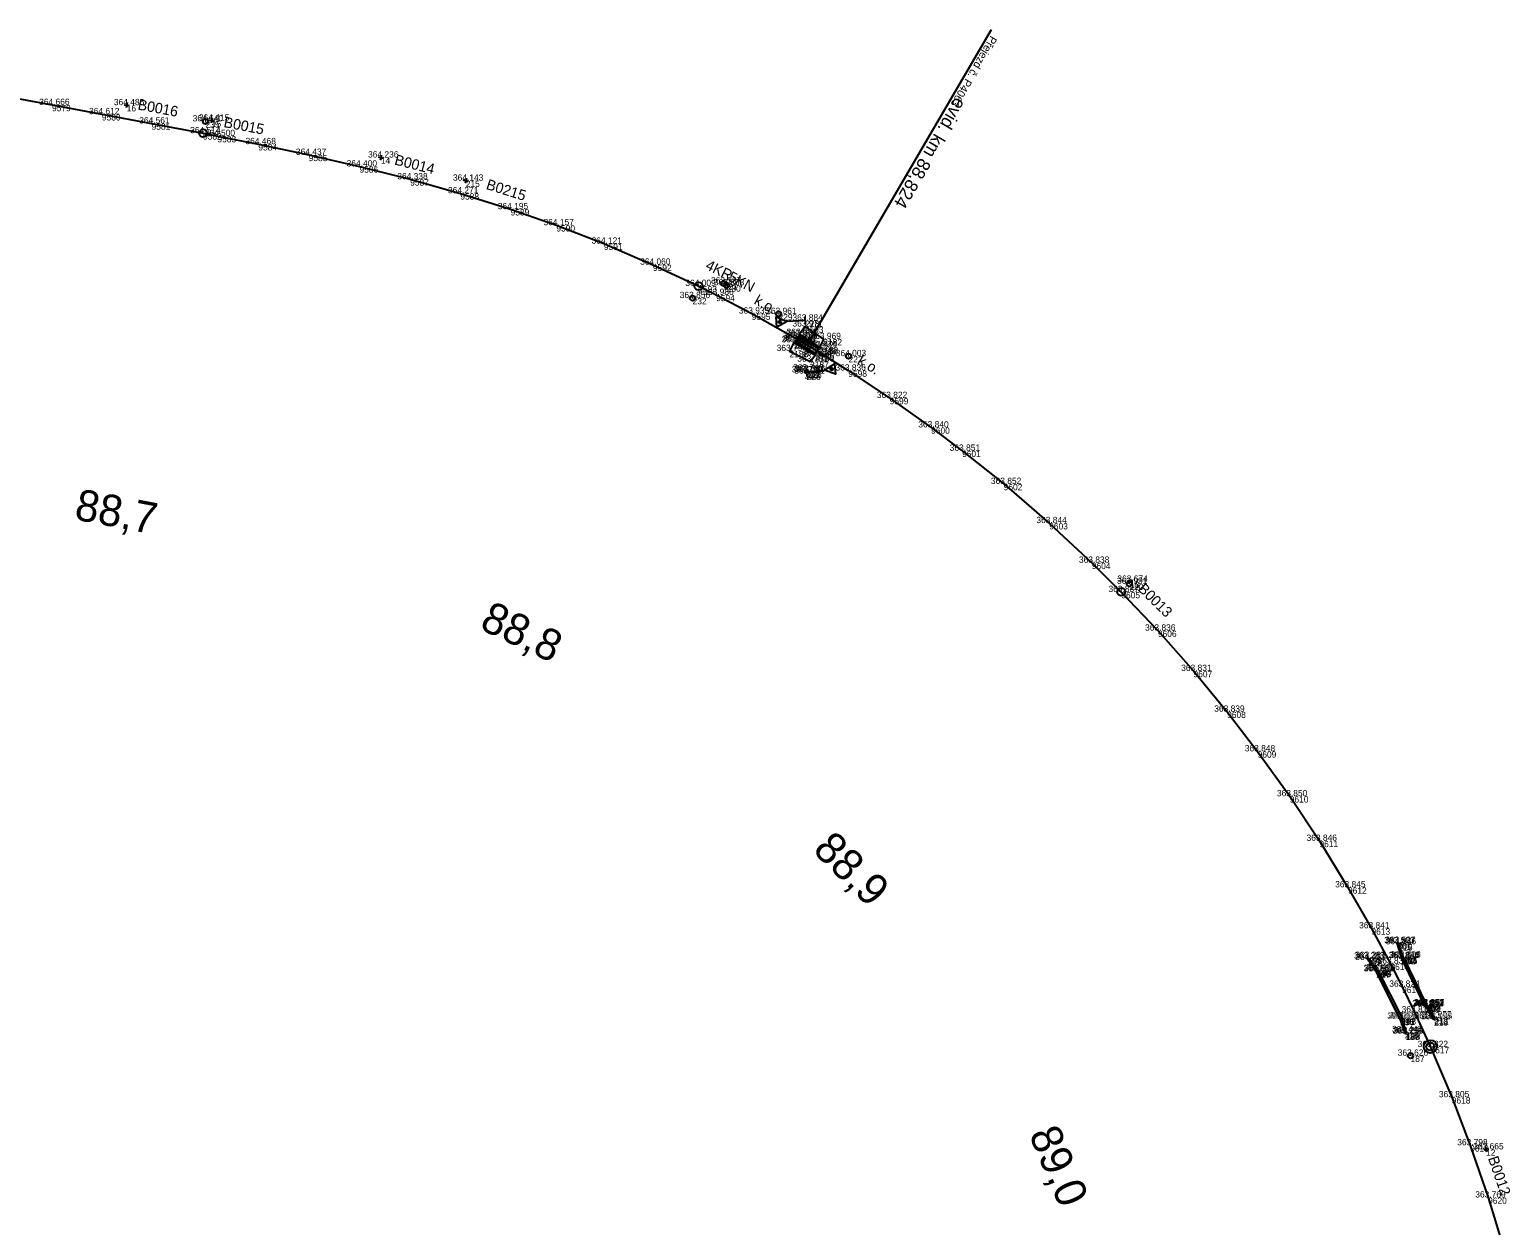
# Model space of a CAD drawing. Extents: x -599511 to -595511, y -1067427 to -1062061.
# Drawn here: x -595924.1 to -595641.5, y -1066766.1 to -1066537.9 of the extents above; entities that cross this region are included whole.
import ezdxf

# ---------------------------------------------------------------- set-up
doc = ezdxf.new("R2010")
doc.units = 0
for name, color, linetype in [('Vrstva 1', 7, 'Continuous'), ('Vrstva 12', 7, 'Continuous'), ('Vrstva 17', 7, 'Continuous'), ('Vrstva 18', 7, 'Continuous'), ('Vrstva 27', 7, 'Continuous'), ('Vrstva 4', 7, 'Continuous'), ('Vrstva 60', 7, 'Continuous'), ('Vrstva 61', 7, 'Continuous'), ('Vrstva 7', 7, 'Continuous')]:
    doc.layers.add(name, color=color, linetype=linetype)

msp = doc.modelspace()

# ---------------------------------------------------------------- linework, layer by layer
at = {"layer": 'Vrstva 1'}
msp.add_lwpolyline([(-595929.53, -1066550.51), (-595919.87, -1066552.29), (-595910.35, -1066554.06), (-595900.86, -1066555.83), (-595891.04, -1066557.7), (-595888.29, -1066558.23), (-595880.48, -1066559.78), (-595870.86, -1066561.82), (-595861.17, -1066564.04), (-595851.49, -1066566.49), (-595841.92, -1066569.17), (-595832.32, -1066572.19), (-595823.59, -1066575.25), (-595814.51, -1066578.77), (-595805.15, -1066582.78), (-595796.52, -1066586.85), (-595793.09, -1066588.55), (-595786.29, -1066592.11), (-595777.84, -1066596.85), (-595773.74, -1066599.3), (-595767.86, -1066602.99), (-595759.96, -1066608.23), (-595752.05, -1066613.85), (-595746.14, -1066618.3), (-595738.2, -1066624.64), (-595729.51, -1066632.11), (-595721.37, -1066639.68), (-595715.74, -1066645.26), (-595708.76, -1066652.62), (-595701.96, -1066660.32), (-595695.54, -1066668.1), (-595689.72, -1066675.67), (-595683.59, -1066684.23), (-595677.93, -1066692.75), (-595672.47, -1066701.63), (-595667.99, -1066709.45), (-595664.37, -1066716.2), (-595662.14, -1066720.6), (-595659.78, -1066725.47), (-595656.72, -1066732.11), (-595652.66, -1066741.68), (-595649.15, -1066750.86), (-595645.72, -1066760.82), (-595642.55, -1066771.26)], dxfattribs=at)
at = {"layer": 'Vrstva 12'}
msp.add_lwpolyline([(-595776.2, -1066603.35), (-595775.95, -1066602.97), (-595775.59, -1066603.18), (-595775.81, -1066603.57)], close=True, dxfattribs=at)
at = {"layer": 'Vrstva 17'}
for points in [[(-595662.83, -1066712.48), (-595661.92, -1066715.05), (-595657.47, -1066724.14), (-595656.02, -1066726.45)], [(-595661.64, -1066729.26), (-595662.5, -1066726.68), (-595667.04, -1066717.65), (-595668.63, -1066715.48)]]:
    msp.add_lwpolyline(points, dxfattribs=at)
at = {"layer": 'Vrstva 18'}
for points in [[(-595655.9, -1066726.71), (-595656.06, -1066726.82), (-595657.62, -1066724.3), (-595657.76, -1066724.35), (-595662.27, -1066715.13), (-595662.17, -1066715.11), (-595663.1, -1066712.29), (-595662.93, -1066712.21), (-595661.99, -1066715.04), (-595661.89, -1066715), (-595657.41, -1066724.14), (-595657.51, -1066724.18)], [(-595661.33, -1066729.49), (-595661.52, -1066729.55), (-595662.44, -1066726.72), (-595662.52, -1066726.75), (-595667.12, -1066717.66), (-595667.04, -1066717.6), (-595668.86, -1066715.22), (-595668.65, -1066715.08), (-595666.88, -1066717.49), (-595666.77, -1066717.44), (-595662.15, -1066726.6), (-595662.25, -1066726.66)]]:
    msp.add_lwpolyline(points, close=True, dxfattribs=at)
at = {"layer": 'Vrstva 27'}
for p, q in [((-595791.66, -1066586.35), (-595791.58, -1066586.39)), ((-595791.11, -1066586.7), (-595791.02, -1066586.75)), ((-595781.21, -1066592.17), (-595781.13, -1066592.22)), ((-595767.85, -1066600.22), (-595767.77, -1066600.27))]:
    msp.add_line(p, q, dxfattribs=at)
for centre in [(-595791.62, -1066586.37), (-595791.07, -1066586.73), (-595781.17, -1066592.19), (-595767.81, -1066600.24)]:
    msp.add_circle(centre, 0.5, dxfattribs=at)
at = {"layer": 'Vrstva 4'}
for p, q in [((-595775.69, -1066598.13), (-595740.51, -1066537.92)), ((-595776.05, -1066594.22), (-595776.12, -1066592.67)), ((-595780.74, -1066593.88), (-595781.1, -1066593.55)), ((-595775.91, -1066602.47), (-595775.76, -1066604.02)), ((-595771.21, -1066602.57), (-595770.84, -1066602.88))]:
    msp.add_line(p, q, dxfattribs=at)
for points in [[(-595776.08, -1066593.45), (-595779.56, -1066593.62), (-595781.51, -1066594.7), (-595781.62, -1066592.71), (-595779.56, -1066593.62)], [(-595775.84, -1066603.24), (-595772.38, -1066602.89), (-595770.48, -1066601.71), (-595770.28, -1066603.7), (-595772.38, -1066602.89)]]:
    msp.add_lwpolyline(points, dxfattribs=at)
for points in [[(-595777.29, -1066596.2), (-595776.17, -1066594.6), (-595772.62, -1066596.98), (-595773.36, -1066598.55)], [(-595775.15, -1066601.29), (-595774.16, -1066600.06), (-595778.24, -1066597.61), (-595779.09, -1066599.26)], [(-595777.95, -1066597.43), (-595777.4, -1066596.46), (-595773.53, -1066598.78), (-595774.11, -1066599.73)]]:
    msp.add_lwpolyline(points, close=True, dxfattribs=at)
for centre in [(-595780.92, -1066593.72), (-595771.03, -1066602.73)]:
    msp.add_circle(centre, 0.248, dxfattribs=at)
at = {"layer": 'Vrstva 60'}
for p, q in [((-595919.87, -1066552.29), (-595919.87, -1066552.29)), ((-595905.61, -1066552.34), (-595905.61, -1066552.34)), ((-595910.35, -1066554.06), (-595910.35, -1066554.06)), ((-595900.86, -1066555.83), (-595900.86, -1066555.83)), ((-595890.57, -1066555.44), (-595890.57, -1066555.44)), ((-595889.37, -1066555.28), (-595889.37, -1066555.28)), ((-595891.04, -1066557.7), (-595891.04, -1066557.7)), ((-595888.29, -1066558.23), (-595888.29, -1066558.23)), ((-595880.48, -1066559.78), (-595880.48, -1066559.78)), ((-595870.86, -1066561.82), (-595870.86, -1066561.82)), ((-595861.17, -1066564.04), (-595861.17, -1066564.04)), ((-595857.09, -1066562.33), (-595857.09, -1066562.33)), ((-595851.49, -1066566.49), (-595851.49, -1066566.49)), ((-595840.88, -1066566.75), (-595840.88, -1066566.75)), ((-595841.92, -1066569.17), (-595841.92, -1066569.17)), ((-595832.32, -1066572.19), (-595832.32, -1066572.19)), ((-595823.59, -1066575.25), (-595823.59, -1066575.25)), ((-595814.51, -1066578.77), (-595814.51, -1066578.77)), ((-595805.15, -1066582.78), (-595805.15, -1066582.78)), ((-595796.52, -1066586.85), (-595796.52, -1066586.85)), ((-595791.62, -1066586.37), (-595791.62, -1066586.37)), ((-595791.07, -1066586.73), (-595791.07, -1066586.73)), ((-595797.58, -1066589.16), (-595797.58, -1066589.16)), ((-595793.09, -1066588.55), (-595793.09, -1066588.55)), ((-595786.29, -1066592.11), (-595786.29, -1066592.11)), ((-595781.17, -1066592.19), (-595781.17, -1066592.19)), ((-595776.17, -1066594.6), (-595776.17, -1066594.6)), ((-595776.08, -1066593.45), (-595776.08, -1066593.45)), ((-595778.24, -1066597.61), (-595778.24, -1066597.61)), ((-595777.95, -1066597.43), (-595777.95, -1066597.43)), ((-595777.84, -1066596.85), (-595777.84, -1066596.85)), ((-595777.4, -1066596.46), (-595777.4, -1066596.46)), ((-595777.29, -1066596.2), (-595777.29, -1066596.2)), ((-595773.53, -1066598.78), (-595773.53, -1066598.78)), ((-595773.36, -1066598.55), (-595773.36, -1066598.55)), ((-595772.62, -1066596.98), (-595772.62, -1066596.98)), ((-595779.09, -1066599.26), (-595779.09, -1066599.26)), ((-595775.15, -1066601.29), (-595775.15, -1066601.29)), ((-595774.16, -1066600.06), (-595774.16, -1066600.06)), ((-595774.11, -1066599.73), (-595774.11, -1066599.73)), ((-595773.74, -1066599.3), (-595773.74, -1066599.3)), ((-595767.81, -1066600.24), (-595767.81, -1066600.24)), ((-595776.2, -1066603.35), (-595776.2, -1066603.35)), ((-595775.95, -1066602.97), (-595775.95, -1066602.97)), ((-595775.84, -1066603.24), (-595775.84, -1066603.24)), ((-595775.81, -1066603.57), (-595775.81, -1066603.57)), ((-595775.59, -1066603.18), (-595775.59, -1066603.18)), ((-595767.86, -1066602.99), (-595767.86, -1066602.99)), ((-595759.96, -1066608.23), (-595759.96, -1066608.23)), ((-595752.05, -1066613.85), (-595752.05, -1066613.85)), ((-595746.14, -1066618.3), (-595746.14, -1066618.3)), ((-595738.2, -1066624.64), (-595738.2, -1066624.64)), ((-595729.51, -1066632.11), (-595729.51, -1066632.11)), ((-595721.37, -1066639.68), (-595721.37, -1066639.68)), ((-595714.21, -1066643.69), (-595714.21, -1066643.69)), ((-595714.05, -1066643.3), (-595714.05, -1066643.3)), ((-595715.74, -1066645.26), (-595715.74, -1066645.26)), ((-595708.76, -1066652.62), (-595708.76, -1066652.62)), ((-595701.96, -1066660.32), (-595701.96, -1066660.32)), ((-595695.54, -1066668.1), (-595695.54, -1066668.1)), ((-595689.72, -1066675.67), (-595689.72, -1066675.67)), ((-595683.59, -1066684.23), (-595683.59, -1066684.23)), ((-595677.93, -1066692.75), (-595677.93, -1066692.75)), ((-595672.47, -1066701.63), (-595672.47, -1066701.63)), ((-595667.99, -1066709.45), (-595667.99, -1066709.45)), ((-595663.1, -1066712.29), (-595663.1, -1066712.29)), ((-595662.93, -1066712.21), (-595662.93, -1066712.21)), ((-595662.83, -1066712.48), (-595662.83, -1066712.48)), ((-595668.86, -1066715.22), (-595668.86, -1066715.22)), ((-595668.65, -1066715.08), (-595668.65, -1066715.08)), ((-595668.63, -1066715.48), (-595668.63, -1066715.48)), ((-595666.88, -1066717.49), (-595666.88, -1066717.49)), ((-595666.77, -1066717.44), (-595666.77, -1066717.44)), ((-595664.37, -1066716.2), (-595664.37, -1066716.2)), ((-595662.27, -1066715.13), (-595662.27, -1066715.13)), ((-595662.17, -1066715.11), (-595662.17, -1066715.11)), ((-595661.99, -1066715.04), (-595661.99, -1066715.04)), ((-595661.92, -1066715.05), (-595661.92, -1066715.05)), ((-595661.89, -1066715), (-595661.89, -1066715)), ((-595667.12, -1066717.66), (-595667.12, -1066717.66)), ((-595667.04, -1066717.6), (-595667.04, -1066717.6)), ((-595667.04, -1066717.65), (-595667.04, -1066717.65)), ((-595662.14, -1066720.6), (-595662.14, -1066720.6)), ((-595659.78, -1066725.47), (-595659.78, -1066725.47)), ((-595657.76, -1066724.35), (-595657.76, -1066724.35)), ((-595657.62, -1066724.3), (-595657.62, -1066724.3)), ((-595657.51, -1066724.18), (-595657.51, -1066724.18)), ((-595657.47, -1066724.14), (-595657.47, -1066724.14)), ((-595657.41, -1066724.14), (-595657.41, -1066724.14)), ((-595662.52, -1066726.75), (-595662.52, -1066726.75)), ((-595662.5, -1066726.68), (-595662.5, -1066726.68)), ((-595662.44, -1066726.72), (-595662.44, -1066726.72)), ((-595662.25, -1066726.66), (-595662.25, -1066726.66)), ((-595662.15, -1066726.6), (-595662.15, -1066726.6)), ((-595656.06, -1066726.82), (-595656.06, -1066726.82)), ((-595656.02, -1066726.45), (-595656.02, -1066726.45)), ((-595655.9, -1066726.71), (-595655.9, -1066726.71)), ((-595661.64, -1066729.26), (-595661.64, -1066729.26)), ((-595661.52, -1066729.55), (-595661.52, -1066729.55)), ((-595661.33, -1066729.49), (-595661.33, -1066729.49)), ((-595660.53, -1066733.76), (-595660.53, -1066733.76)), ((-595656.72, -1066732.11), (-595656.72, -1066732.11)), ((-595652.66, -1066741.68), (-595652.66, -1066741.68)), ((-595649.15, -1066750.86), (-595649.15, -1066750.86)), ((-595646.1, -1066751.64), (-595646.1, -1066751.64)), ((-595645.72, -1066760.82), (-595645.72, -1066760.82))]:
    msp.add_line(p, q, dxfattribs=at)
at = {"layer": 'Vrstva 7'}
for p, q in [((-595906.1, -1066552.25), (-595905.12, -1066552.43)), ((-595905.52, -1066551.85), (-595905.7, -1066552.83)), ((-595890.62, -1066555.43), (-595890.52, -1066555.45)), ((-595889.86, -1066555.18), (-595888.88, -1066555.37)), ((-595889.28, -1066554.79), (-595889.46, -1066555.77)), ((-595856.97, -1066561.85), (-595857.21, -1066562.82)), ((-595857.58, -1066562.21), (-595856.61, -1066562.46)), ((-595841.36, -1066566.6), (-595840.4, -1066566.9)), ((-595840.73, -1066566.27), (-595841.03, -1066567.23)), ((-595797.63, -1066589.13), (-595797.54, -1066589.18)), ((-595714.41, -1066642.95), (-595713.7, -1066643.66)), ((-595713.7, -1066642.95), (-595714.4, -1066643.66)), ((-595714.25, -1066643.65), (-595714.18, -1066643.72)), ((-595660.55, -1066733.71), (-595660.51, -1066733.8)), ((-595646.26, -1066751.17), (-595645.94, -1066752.11)), ((-595645.63, -1066751.48), (-595646.57, -1066751.8))]:
    msp.add_line(p, q, dxfattribs=at)
for centre, radius in [((-595890.57, -1066555.44), 0.5), ((-595891.02, -1066557.7), 0.75), ((-595796.44, -1066586.89), 0.75), ((-595797.58, -1066589.16), 0.5), ((-595714.21, -1066643.69), 0.5), ((-595715.76, -1066645.24), 0.75), ((-595656.77, -1066732.02), 1.25), ((-595656.77, -1066732.02), 0.752), ((-595660.53, -1066733.76), 0.5)]:
    msp.add_circle(centre, radius, dxfattribs=at)

# ---------------------------------------------------------------- texts
at = {"layer": 'Vrstva 27'}
for s, rotation, p in [('4KR', 333.5891, (-595795.29, -1066583.54)), ('5KN', 332.3735, (-595790.99, -1066585.73)), ('k.o.', 330.7363, (-595786.01, -1066590.17)), ('k.o.', 327.9482, (-595766.26, -1066601.58))]:
    msp.add_text(s, height=2, rotation=rotation, dxfattribs=at).set_placement(p)
at = {"layer": 'Vrstva 4'}
for s, height, p in [('Přejezd č. P4063', 1.5, (-595740.68, -1066538.96)), ('evid. km 88,824', 2.5, (-595747.37, -1066550.69))]:
    msp.add_text(s, height=height, rotation=239.7005, dxfattribs=at).set_placement(p)
at = {"layer": 'Vrstva 60'}
for s, p in [('9579', (-595919.87, -1066553.49)), ('16', (-595905.61, -1066553.54)), ('9580', (-595910.35, -1066555.26)), ('9581', (-595900.86, -1066557.03)), ('235', (-595890.57, -1066556.64)), ('15', (-595889.37, -1066556.48)), ('9582', (-595891.04, -1066558.9)), ('9583', (-595888.29, -1066559.43)), ('9584', (-595880.48, -1066560.98)), ('9585', (-595870.86, -1066563.02)), ('9586', (-595861.17, -1066565.24)), ('14', (-595857.09, -1066563.53)), ('9587', (-595851.49, -1066567.69)), ('215', (-595840.88, -1066567.95)), ('9588', (-595841.92, -1066570.37)), ('9589', (-595832.32, -1066573.39)), ('9590', (-595823.59, -1066576.45)), ('9591', (-595814.51, -1066579.97)), ('9592', (-595805.15, -1066583.98)), ('9593', (-595796.52, -1066588.05)), ('231', (-595791.62, -1066587.57)), ('230', (-595791.07, -1066587.93)), ('232', (-595797.58, -1066590.35)), ('9594', (-595793.09, -1066589.75)), ('9595', (-595786.29, -1066593.31)), ('229', (-595781.17, -1066593.39)), ('2193', (-595776.17, -1066595.8)), ('228', (-595776.08, -1066594.65)), ('2189', (-595778.24, -1066598.81)), ('2190', (-595777.95, -1066598.63)), ('9596', (-595777.84, -1066598.05)), ('2191', (-595777.4, -1066597.66)), ('2192', (-595777.29, -1066597.4)), ('2184', (-595773.53, -1066599.98)), ('2183', (-595773.36, -1066599.75)), ('2182', (-595772.62, -1066598.18)), ('2188', (-595779.09, -1066600.46)), ('2187', (-595775.15, -1066602.49)), ('2186', (-595774.16, -1066601.26)), ('2185', (-595774.11, -1066600.93)), ('9597', (-595773.74, -1066600.5)), ('222', (-595767.81, -1066601.44)), ('225', (-595776.2, -1066604.55)), ('224', (-595775.95, -1066604.17)), ('227', (-595775.84, -1066604.44)), ('226', (-595775.81, -1066604.77)), ('223', (-595775.59, -1066604.38)), ('9598', (-595767.86, -1066604.19)), ('9599', (-595759.96, -1066609.43)), ('9600', (-595752.05, -1066615.05)), ('9601', (-595746.14, -1066619.5)), ('9602', (-595738.2, -1066625.84)), ('9603', (-595729.51, -1066633.31)), ('9604', (-595721.37, -1066640.88)), ('220', (-595714.21, -1066644.89)), ('13', (-595714.05, -1066644.5)), ('9605', (-595715.74, -1066646.46)), ('9606', (-595708.76, -1066653.82)), ('9607', (-595701.96, -1066661.52)), ('9608', (-595695.54, -1066669.3)), ('9609', (-595689.72, -1066676.87)), ('9610', (-595683.59, -1066685.43)), ('9611', (-595677.93, -1066693.95)), ('9612', (-595672.47, -1066702.83)), ('9613', (-595667.99, -1066710.65)), ('201', (-595663.1, -1066713.49)), ('200', (-595662.93, -1066713.41)), ('215', (-595662.83, -1066713.68)), ('199', (-595668.86, -1066716.42)), ('216', (-595668.63, -1066716.68)), ('198', (-595668.65, -1066716.28)), ('195', (-595666.88, -1066718.69)), ('194', (-595666.77, -1066718.64)), ('9614', (-595664.37, -1066717.4)), ('202', (-595662.27, -1066716.33)), ('203', (-595662.17, -1066716.31)), ('204', (-595661.99, -1066716.24)), ('214', (-595661.92, -1066716.25)), ('205', (-595661.89, -1066716.2)), ('197', (-595667.12, -1066718.86)), ('217', (-595667.04, -1066718.85)), ('196', (-595667.04, -1066718.8)), ('9615', (-595662.14, -1066721.8)), ('9616', (-595659.78, -1066726.67)), ('206', (-595657.76, -1066725.55)), ('207', (-595657.62, -1066725.5)), ('208', (-595657.51, -1066725.38)), ('213', (-595657.47, -1066725.34)), ('209', (-595657.41, -1066725.34)), ('218', (-595662.5, -1066727.88)), ('190', (-595662.52, -1066727.95)), ('191', (-595662.44, -1066727.92)), ('192', (-595662.25, -1066727.86)), ('193', (-595662.15, -1066727.8)), ('210', (-595656.06, -1066728.02)), ('212', (-595656.02, -1066727.65)), ('211', (-595655.9, -1066727.91)), ('219', (-595661.64, -1066730.46)), ('189', (-595661.52, -1066730.75)), ('188', (-595661.33, -1066730.69)), ('187', (-595660.53, -1066734.96)), ('9617', (-595656.72, -1066733.31)), ('9618', (-595652.66, -1066742.88)), ('9619', (-595649.15, -1066752.06)), ('12', (-595646.1, -1066752.84)), ('9620', (-595645.72, -1066762.02))]:
    msp.add_text(s, height=1.2, dxfattribs=at).set_placement(p)
at = {"layer": 'Vrstva 61'}
for s, p in [('364.666', (-595922.32, -1066552.29)), ('364.612', (-595912.8, -1066554.06)), ('364.485', (-595908.06, -1066552.34)), ('364.561', (-595903.22, -1066555.83)), ('364.640', (-595893.02, -1066555.44)), ('364.415', (-595891.83, -1066555.28)), ('364.514', (-595893.49, -1066557.7)), ('364.500', (-595890.74, -1066558.23)), ('364.468', (-595882.93, -1066559.78)), ('364.437', (-595873.31, -1066561.82)), ('364.236', (-595859.54, -1066562.33)), ('364.400', (-595863.62, -1066564.04)), ('364.338', (-595853.95, -1066566.49)), ('364.143', (-595843.33, -1066566.75)), ('364.271', (-595844.28, -1066569.17)), ('364.195', (-595834.77, -1066572.19)), ('364.157', (-595826.04, -1066575.25)), ('364.121', (-595816.87, -1066578.77)), ('364.060', (-595807.6, -1066582.78)), ('364.009', (-595798.97, -1066586.85)), ('363.986', (-595795.54, -1066588.55)), ('363.787', (-595794.07, -1066586.37)), ('363.803', (-595793.52, -1066586.73)), ('363.856', (-595800.04, -1066589.16)), ('363.935', (-595788.75, -1066592.11)), ('363.961', (-595783.53, -1066592.19)), ('363.884', (-595778.53, -1066593.45)), ('363.873', (-595780.29, -1066596.85)), ('363.971', (-595779.75, -1066596.46)), ('363.981', (-595779.65, -1066596.2)), ('363.971', (-595778.52, -1066594.6)), ('363.969', (-595775.07, -1066596.98)), ('363.794', (-595781.54, -1066599.26)), ('363.851', (-595780.6, -1066597.61)), ('363.880', (-595780.4, -1066597.43)), ('363.877', (-595776.56, -1066599.73)), ('363.860', (-595776.19, -1066599.3)), ('363.945', (-595775.98, -1066598.78)), ('363.976', (-595775.81, -1066598.55)), ('363.783', (-595777.6, -1066601.29)), ('363.857', (-595776.61, -1066600.06)), ('364.003', (-595770.26, -1066600.24)), ('363.730', (-595778.65, -1066603.35)), ('363.740', (-595778.4, -1066602.97)), ('363.681', (-595778.2, -1066603.24)), ('363.761', (-595778.17, -1066603.57)), ('363.746', (-595778.05, -1066603.18)), ('363.836', (-595770.31, -1066602.99)), ('363.822', (-595762.41, -1066608.23)), ('363.840', (-595754.5, -1066613.85)), ('363.851', (-595748.5, -1066618.3)), ('363.852', (-595740.64, -1066624.64)), ('363.844', (-595731.96, -1066632.11)), ('363.838', (-595723.83, -1066639.68)), ('363.991', (-595716.57, -1066643.69)), ('363.674', (-595716.5, -1066643.3)), ('363.837', (-595718.19, -1066645.26)), ('363.836', (-595711.21, -1066652.62)), ('363.831', (-595704.31, -1066660.32)), ('363.839', (-595698, -1066668.1)), ('363.848', (-595692.17, -1066675.67)), ('363.850', (-595686.04, -1066684.23)), ('363.846', (-595680.38, -1066692.75)), ('363.845', (-595674.92, -1066701.63)), ('363.841', (-595670.35, -1066709.45)), ('363.503', (-595665.56, -1066712.29)), ('363.507', (-595665.38, -1066712.21)), ('364.646', (-595665.28, -1066712.48)), ('363.283', (-595671.31, -1066715.22)), ('363.287', (-595671.1, -1066715.08)), ('364.433', (-595671.09, -1066715.48)), ('363.834', (-595664.72, -1066715.13)), ('363.848', (-595664.62, -1066715.11)), ('363.863', (-595664.44, -1066715.04)), ('364.980', (-595664.37, -1066715.05)), ('363.868', (-595664.35, -1066715)), ('363.652', (-595669.48, -1066717.6)), ('363.661', (-595669.48, -1066717.66)), ('364.761', (-595669.39, -1066717.65)), ('363.646', (-595669.33, -1066717.49)), ('363.636', (-595669.22, -1066717.44)), ('363.830', (-595666.82, -1066716.2)), ('363.824', (-595664.59, -1066720.6)), ('363.834', (-595660.21, -1066724.35)), ('363.842', (-595660.07, -1066724.3)), ('363.850', (-595659.96, -1066724.18)), ('363.857', (-595659.86, -1066724.14)), ('364.971', (-595659.83, -1066724.14)), ('363.663', (-595664.97, -1066726.75)), ('364.774', (-595664.95, -1066726.68)), ('363.657', (-595664.89, -1066726.72)), ('363.646', (-595664.7, -1066726.66)), ('363.641', (-595664.5, -1066726.6)), ('363.815', (-595662.23, -1066725.47)), ('363.493', (-595658.51, -1066726.82)), ('364.655', (-595658.47, -1066726.45)), ('363.496', (-595658.36, -1066726.71)), ('364.442', (-595664.08, -1066729.26)), ('363.293', (-595663.97, -1066729.55)), ('363.290', (-595663.78, -1066729.49)), ('363.822', (-595659.17, -1066732.11)), ('363.626', (-595662.98, -1066733.76)), ('363.805', (-595655.12, -1066741.68)), ('363.798', (-595651.61, -1066750.86)), ('363.665', (-595648.56, -1066751.64)), ('363.769', (-595648.17, -1066760.82))]:
    msp.add_text(s, height=1.2, dxfattribs=at).set_placement(p)
at = {"layer": 'Vrstva 7'}
for s, height, rotation, p in [('B0016', 2, 349.3898, (-595903.61, -1066553.15)), ('B0015', 2, 349.0673, (-595887.21, -1066556.5)), ('B0014', 2, 345.8092, (-595854.62, -1066563.65)), ('B0215', 2, 342.5564, (-595837.14, -1066568.31)), ('88,7', 6, 349.2409, (-595915.79, -1066631.37)), ('B0013', 2, 315.286, (-595712.7, -1066644.81)), ('88,8', 6, 334.8014, (-595838.48, -1066652.21)), ('88,9', 6, 315.286, (-595774.85, -1066694.68)), ('89,0', 6, 292.9981, (-595733.45, -1066748.73)), ('B0012', 2, 289.0199, (-595645.76, -1066753.32))]:
    msp.add_text(s, height=height, rotation=rotation, dxfattribs=at).set_placement(p)

doc.saveas('drawing.dxf')
